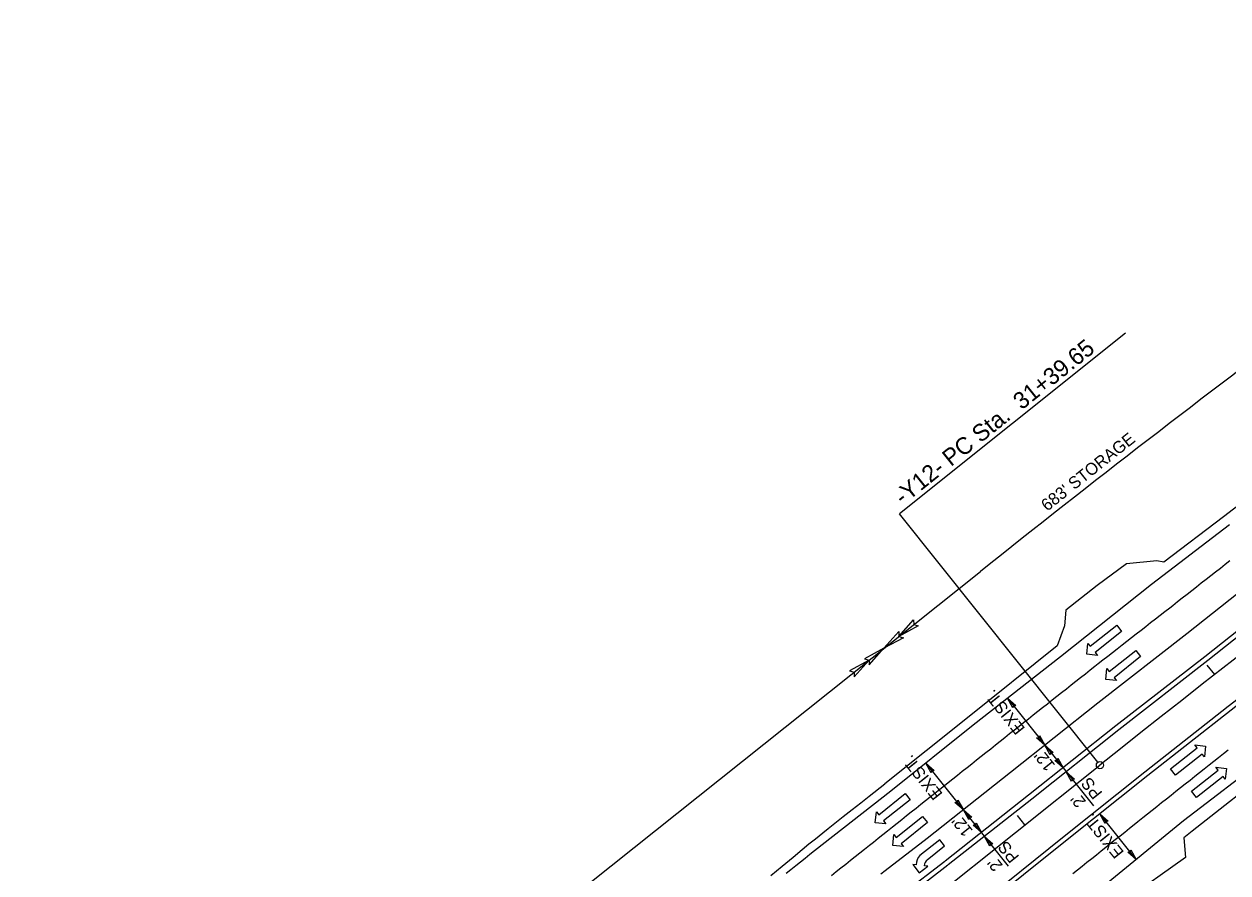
# Model space of a CAD drawing. Extents: x 472216 to 481979, y 489069 to 507339.
# Drawn here: x 473629 to 474126.1, y 506517.1 to 506867.8 of the extents above; entities that cross this region are included whole.
import ezdxf

# ---------------------------------------------------------------- set-up
doc = ezdxf.new("R2010")
doc.units = 0
for name, color, linetype in [('Old_Level_12', 7, 'Continuous'), ('Prop Drainage Structure Outlet Berm Ditch 850 10 CELL', 7, 'Continuous'), ('Prop Drainage Structure Pipe CSP 15in', 7, 'Continuous'), ('Prop Drainage Structure Pipe RCP 24in Class III Label', 7, 'Continuous'), ('Prop Drainage Structure Pipe Side Drain 15in Label', 7, 'Continuous'), ('Prop Erosion Embankment Toe Protection CELL', 7, 'Continuous'), ('Prop Erosion Embankment Toe Protection Label', 7, 'Continuous'), ('Sheet Block Revision CELL', 7, 'Continuous'), ('Sheet North Arrow Point CELL', 7, 'Continuous'), ('Sheet PE Seal Cell', 7, 'Continuous')]:
    doc.layers.add(name, color=color, linetype=linetype)

msp = doc.modelspace()

# ---------------------------------------------------------------- linework, layer by layer
at = {"layer": 'Old_Level_12'}
for p in [(474083.81, 506740.02), (474072.35, 506562.79)]:
    msp.add_line(p, (473990.53, 506665.37), dxfattribs=at)
msp.add_circle((474073.29, 506561.61), 1.5, dxfattribs=at)
at = {"layer": 'Prop Drainage Structure Outlet Berm Ditch 850 10 CELL'}
for points in [[(473998.28, 506619.18), (473990.27, 506614.78), (473996.35, 506621.68), (473996.45, 506619.71)], [(473992.1, 506614.26), (473984.1, 506609.86), (473990.17, 506616.75), (473990.27, 506614.78)], [(473978.03, 506603.03), (473984.1, 506609.86), (473976.02, 506605.47), (473977.92, 506604.93)], [(473971.85, 506598.11), (473977.92, 506604.93), (473969.85, 506600.54), (473971.74, 506600.01)], [(474037.31, 506585.23), (474035.1, 506589.23), (474038.55, 506586.2), (474037.57, 506586.14)], [(474048.34, 506573.85), (474050.54, 506569.86), (474047.09, 506572.89), (474048.08, 506572.94)], [(474052.75, 506565.86), (474050.54, 506569.86), (474054, 506566.82), (474053.01, 506566.77)], [(474003.65, 506558.48), (474001.44, 506562.47), (474004.89, 506559.44), (474003.91, 506559.39)], [(474055.84, 506564.45), (474058.05, 506560.45), (474054.6, 506563.49), (474055.58, 506563.54)], [(474061.5, 506554.89), (474059.3, 506558.89), (474062.75, 506555.86), (474061.77, 506555.81)], [(474014.66, 506547.12), (474016.87, 506543.13), (474013.42, 506546.16), (474014.4, 506546.21)], [(474019.08, 506539.13), (474016.87, 506543.13), (474020.32, 506540.09), (474019.34, 506540.04)], [(474075.4, 506537.46), (474073.2, 506541.46), (474076.65, 506538.43), (474075.67, 506538.38)], [(474022.15, 506537.74), (474024.35, 506533.74), (474020.9, 506536.78), (474021.88, 506536.83)], [(474027.81, 506528.18), (474025.6, 506532.18), (474029.05, 506529.15), (474028.07, 506529.1)], [(474086.04, 506526.6), (474088.24, 506522.6), (474084.79, 506525.63), (474085.77, 506525.68)]]:
    msp.add_lwpolyline(points, close=True, dxfattribs=at)
at = {"layer": 'Prop Drainage Structure Pipe RCP 24in Class III Label'}
for points in [[(474370.72, 506764.71), (474340.99, 506743.68), (474302.6, 506716.52), (474269.35, 506692.49), (474236.2, 506668.03), (474201.05, 506641.52), (474163.16, 506612.28), (474127.52, 506584.26), (474093.1, 506557.25), (474059.03, 506530.23), (474024.32, 506502.31)], [(474384.66, 506744.82), (474356.58, 506725.38), (474317.77, 506697.98), (474283.49, 506673.01), (474250.94, 506648.79), (474215.97, 506622.54), (474177.15, 506592.68), (474142.36, 506565.08), (474107.83, 506538.54), (474073.61, 506510.68), (474038.16, 506482.59)], [(474126.73, 506660.86), (474094.52, 506636.19), (474056.95, 506606.33), (474020.96, 506578.17), (473986.89, 506550.78)], [(474172.98, 506650.93), (474148.43, 506631.59), (474116.53, 506606.38), (474079.83, 506577.82), (474043.84, 506549.13), (474009.36, 506521.92)], [(473986.89, 506550.78), (473955.45, 506526.18), (473953.5, 506524.62), (473951.55, 506523.06), (473949.6, 506521.49), (473947.65, 506519.93), (473945.7, 506518.37), (473943.75, 506516.8)], [(474009.26, 506521.83), (473992, 506508.53), (473990.3, 506507.18), (473981.12, 506499.85), (473971.51, 506492.2), (473962.33, 506484.88), (473952.75, 506477.25), (473943.6, 506469.95), (473934.44, 506462.65), (473924.91, 506455.03), (473915.79, 506447.72), (473906.27, 506440.08), (473897.18, 506432.8), (473888.11, 506425.54), (473877.44, 506416.99), (473868.47, 506409.76), (473855.37, 506399.15), (473839.04, 506386.02), (473812.65, 506364.8), (473778.08, 506337.11), (473740.52, 506306.99), (473705.74, 506279.1), (473689.48, 506266.16)]]:
    msp.add_lwpolyline(points, dxfattribs=at)
at = {"layer": 'Prop Drainage Structure Pipe Side Drain 15in Label'}
for p, q in [((474069.24, 506610.69), (474080.19, 506619.42)), ((474080.19, 506619.42), (474082.24, 506616.84)), ((474082.24, 506616.84), (474071.3, 506608.11)), ((474067.84, 506607.4), (474068.3, 506611.86)), ((474068.3, 506611.86), (474069.24, 506610.69)), ((474072.23, 506606.94), (474067.84, 506607.4)), ((474071.3, 506608.11), (474072.23, 506606.94)), ((474077.08, 506600.29), (474088.03, 506609.01)), ((474090.09, 506606.43), (474079.14, 506597.71)), ((474088.03, 506609.01), (474090.09, 506606.43)), ((474075.68, 506596.99), (474076.15, 506601.46)), ((474076.15, 506601.46), (474077.08, 506600.29)), ((474080.08, 506596.53), (474075.68, 506596.99)), ((474079.14, 506597.71), (474080.08, 506596.53)), ((474113.42, 506568.76), (474112.49, 506569.93)), ((474112.49, 506569.93), (474116.88, 506569.47)), ((474102.47, 506560.03), (474113.42, 506568.76)), ((474115.48, 506566.18), (474104.53, 506557.45)), ((474116.41, 506565.01), (474115.48, 506566.18)), ((474116.88, 506569.47), (474116.41, 506565.01)), ((474104.53, 506557.45), (474102.47, 506560.03)), ((474122.05, 506559.53), (474121.11, 506560.7)), ((474121.11, 506560.7), (474125.51, 506560.24)), ((474125.51, 506560.24), (474125.04, 506555.77)), ((474111.1, 506550.8), (474122.05, 506559.53)), ((474124.1, 506556.95), (474113.16, 506548.22)), ((474125.04, 506555.77), (474124.1, 506556.95)), ((473981.92, 506541.1), (473992.86, 506549.83)), ((473992.86, 506549.83), (473994.92, 506547.25)), ((474113.16, 506548.22), (474111.1, 506550.8)), ((473994.92, 506547.25), (473983.97, 506538.52)), ((473980.51, 506537.81), (473980.98, 506542.28)), ((473980.98, 506542.28), (473981.92, 506541.1)), ((473989.12, 506531.71), (474000.07, 506540.44)), ((474000.07, 506540.44), (474002.13, 506537.86)), ((473984.91, 506537.35), (473980.51, 506537.81)), ((473983.97, 506538.52), (473984.91, 506537.35)), ((474002.13, 506537.86), (473991.18, 506529.13)), ((473987.72, 506528.42), (473988.19, 506532.89)), ((473988.19, 506532.89), (473989.12, 506531.71)), ((474007.1, 506530.8), (473998.85, 506524.22)), ((474009.16, 506528.22), (474007.1, 506530.8)), ((473992.11, 506527.96), (473987.72, 506528.42)), ((473991.18, 506529.13), (473992.11, 506527.96)), ((474002, 506522.52), (474009.16, 506528.22)), ((473997.46, 506520.43), (473995.99, 506520.6)), ((473995.99, 506520.6), (473998.69, 506517.13)), ((474002.24, 506519.89), (474000.77, 506520.06)), ((473998.69, 506517.13), (474002.24, 506519.89))]:
    msp.add_line(p, q, dxfattribs=at)
for centre, radius, start, end in [((474002.7, 506520.67), 5.25, 137.2367, 182.5484), ((474004.03, 506519.96), 3.27, 128.5607, 178.2188)]:
    msp.add_arc(centre, radius, start, end, dxfattribs=at)
at = {"layer": 'Prop Erosion Embankment Toe Protection CELL'}
for points in [[(474369.75, 506766.1), (474340.05, 506745.13), (474301.85, 506717.98), (474268.33, 506693.86), (474235.43, 506669.19), (474200.05, 506642.68), (474162.47, 506613.64), (474126.28, 506585.83), (474091.81, 506558.75), (474057.86, 506531.55), (474023.33, 506503.79)], [(474387.6, 506740.62), (474358.36, 506719.73), (474320.79, 506693.67), (474285.93, 506668.84), (474254.31, 506645.41), (474219.39, 506618.59), (474216.67, 506612.87), (474216.4, 506608.76), (474194.01, 506592.14), (474188.13, 506593.85), (474180.54, 506588.65), (474145.41, 506561.02), (474111.38, 506534.37), (474107.89, 506531.62), (474108.56, 506523.49), (474083.47, 506505.59), (474077.48, 506507.4), (474053.73, 506488.4), (474050.59, 506483.44), (474051.16, 506479.54), (474044.66, 506473.86)], [(474179.11, 506706.1), (474173.3, 506707.15), (474156.67, 506693.48), (474155.96, 506688.89), (474149.68, 506683.54), (474124.27, 506664.21), (474099.67, 506645.48), (474096.82, 506646.06), (474084.3, 506644.78), (474072.14, 506635.84), (474059.14, 506625.68), (474058.6, 506619.19), (474055.57, 506610.84), (474018.55, 506581.08), (473984.44, 506553.89)], [(474174.22, 506649.36), (474149.67, 506630.02), (474117.76, 506604.81), (474081.07, 506576.25), (474045.09, 506547.56), (474010.6, 506520.35)], [(473937.4, 506515.96), (473939.77, 506517.92), (473942.1, 506519.87), (473946.59, 506523.64), (473950.26, 506526.69), (473953.12, 506529.03), (473955.83, 506531.21), (473958.81, 506533.58), (473961.04, 506535.35), (473963.87, 506537.61), (473967.29, 506540.33), (473970.96, 506543.26), (473974.52, 506546.09), (473977.99, 506548.83), (473984.44, 506553.89)], [(474010.48, 506520.25), (473993.23, 506506.96), (473991.54, 506505.62), (473982.36, 506498.29), (473972.76, 506490.64), (473963.58, 506483.31), (473954, 506475.69), (473944.84, 506468.38), (473935.69, 506461.09), (473926.16, 506453.46), (473917.05, 506446.16), (473907.52, 506438.52), (473898.43, 506431.24), (473889.36, 506423.98), (473878.69, 506415.43), (473869.73, 506408.21), (473856.63, 506397.6), (473840.3, 506384.46), (473813.9, 506363.24), (473779.33, 506335.55), (473741.77, 506305.43), (473706.99, 506277.53), (473690.73, 506264.59)]]:
    msp.add_lwpolyline(points, dxfattribs=at)
at = {"layer": 'Prop Erosion Embankment Toe Protection Label'}
for points in [[(474167.06, 506661.38), (474165.57, 506660.37), (474141, 506641.01), (474109.12, 506615.82), (474072.4, 506587.24), (474036.39, 506558.53), (474001.93, 506531.34)], [(474126.92, 506645.97), (474124.95, 506644.43), (474122.99, 506642.89), (474121.02, 506641.35), (474119.06, 506639.81), (474117.09, 506638.27), (474115.13, 506636.72), (474113.16, 506635.18), (474111.19, 506633.64), (474109.23, 506632.1), (474107.26, 506630.56), (474105.3, 506629.01), (474103.33, 506627.47), (474102.08, 506626.49), (474100.11, 506624.95), (474098.14, 506623.41), (474096.17, 506621.88), (474094.21, 506620.34), (474092.24, 506618.8), (474090.27, 506617.26), (474088.3, 506615.72), (474086.33, 506614.19), (474084.36, 506612.65), (474082.39, 506611.11), (474080.43, 506609.57), (474078.46, 506608.03), (474076.49, 506606.49), (474074.52, 506604.96), (474072.55, 506603.42), (474071.17, 506602.34), (474069.21, 506600.79), (474067.25, 506599.24), (474065.29, 506597.69), (474063.33, 506596.14), (474061.37, 506594.59), (474059.41, 506593.04), (474057.46, 506591.49), (474055.5, 506589.94), (474053.54, 506588.39), (474051.58, 506586.84), (474049.62, 506585.29), (474047.66, 506583.74), (474045.7, 506582.19), (474043.74, 506580.64), (474041.78, 506579.09), (474039.89, 506577.59), (474037.94, 506576.03), (474035.98, 506574.48), (474034.03, 506572.92), (474032.07, 506571.37), (474030.12, 506569.81), (474028.16, 506568.26), (474026.21, 506566.7), (474024.25, 506565.15), (474022.3, 506563.59), (474020.34, 506562.04), (474018.39, 506560.48), (474016.43, 506558.92), (474014.48, 506557.37), (474012.52, 506555.81), (474010.57, 506554.26), (474009.05, 506553.05), (474007.1, 506551.5), (474005.15, 506549.94), (474003.19, 506548.38), (474001.24, 506546.83), (473999.29, 506545.27), (473997.33, 506543.71), (473995.38, 506542.16), (473993.42, 506540.6), (473991.47, 506539.04), (473989.52, 506537.49), (473987.56, 506535.93), (473985.61, 506534.37), (473983.66, 506532.82), (473981.7, 506531.26), (473979.75, 506529.7), (473978.07, 506528.36), (473976.11, 506526.8), (473974.16, 506525.25), (473972.21, 506523.69), (473970.26, 506522.13), (473968.31, 506520.57), (473966.35, 506519.01), (473964.4, 506517.45), (473962.45, 506515.89)], [(474062.07, 506516.79), (474064.02, 506518.35), (474065.97, 506519.91), (474067.92, 506521.47), (474069.87, 506523.04), (474071.82, 506524.6), (474073.77, 506526.16), (474075.72, 506527.72), (474077.67, 506529.29), (474079.62, 506530.85), (474081.57, 506532.41), (474083.52, 506533.97), (474085.47, 506535.53), (474087.41, 506537.1), (474088.97, 506538.34), (474090.92, 506539.9), (474092.88, 506541.45), (474094.84, 506543), (474096.79, 506544.56), (474098.75, 506546.11), (474100.7, 506547.67), (474102.66, 506549.22), (474104.62, 506550.78), (474106.57, 506552.33), (474108.53, 506553.89), (474110.48, 506555.44), (474112.44, 506557), (474114.39, 506558.55), (474116.35, 506560.1), (474118.31, 506561.66), (474120.26, 506563.21), (474122.28, 506564.81), (474124.24, 506566.36), (474126.21, 506567.9)], [(474001.93, 506531.34), (473984.6, 506517.98), (473982.81, 506516.56)]]:
    msp.add_lwpolyline(points, dxfattribs=at)
at = {"layer": 'Sheet Block Revision CELL'}
for p, q in [((473636.98, 506333.01), (474023.96, 506641.65)), ((474035.1, 506589.23), (474070.59, 506544.73)), ((474001.44, 506562.47), (474035.41, 506519.88)), ((474088.24, 506522.6), (474073.2, 506541.46))]:
    msp.add_line(p, q, dxfattribs=at)
msp.add_arc((477640.44, 502107.22), 5800, 125.097303, 128.574377, dxfattribs=at)
at = {"layer": 'Sheet North Arrow Point CELL'}
msp.add_line((473181.18, 505850.11), (474073.29, 506561.61), dxfattribs=at)
msp.add_arc((477689.76, 502027.18), 5800, 114.972604, 128.574377, dxfattribs=at)
at = {"layer": 'Sheet PE Seal Cell'}
for p, q in [((474120.67, 506599), (474117.59, 506602.94)), ((474042.29, 506536.89), (474039.17, 506540.8))]:
    msp.add_line(p, q, dxfattribs=at)

# ---------------------------------------------------------------- texts
at = {"layer": 'Old_Level_12'}
msp.add_text('-Y12- PC Sta.  31+39.65', height=7, rotation=38.6712, dxfattribs=at).set_placement((473991.84, 506668.79))
at = {"layer": 'Prop Drainage Structure Pipe CSP 15in'}
for s, rotation, p in [("683' STORAGE", 38.474, (474051.49, 506666.26)), ('EXIST.', 128.5744, (474042.59, 506576.75)), ('EXIST.', 128.5744, (474008.58, 506549.72)), ("12'", 128.6712, (474055.04, 506561.58)), ('PS', 128.6712, (474074.55, 506550.09)), ("2' ", 128.6712, (474067.76, 506546.58)), ("12'", 128.6712, (474021.03, 506534.55)), ('EXIST.', 128.9644, (474083.44, 506525.62)), ('PS', 128.6712, (474040.2, 506523.74)), ("2' ", 128.6712, (474033.41, 506520.22))]:
    msp.add_text(s, height=5, rotation=rotation, dxfattribs=at).set_placement(p)

doc.saveas('drawing.dxf')
